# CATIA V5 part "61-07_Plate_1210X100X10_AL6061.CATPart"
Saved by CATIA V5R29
Part number: 61-07_Plate_580X100X10_AL6061
Bounding box of the stored display mesh (mm): x -290 to 290, y 0 to 10, z -50 to 50
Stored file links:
  C:\Users\Administrator\Desktop\10-14 작업\stopper\61-07_Plate_1210X100X10_AL6061.CATPart
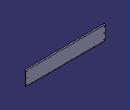
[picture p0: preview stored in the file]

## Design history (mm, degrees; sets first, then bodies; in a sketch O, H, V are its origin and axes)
Body1 (main body)
  Sketch1 on zx-plane, origin (0, 0, 0), H (-1, 0, 0), V (0, 0, 1)
    line L1 (290, 50) -> (290, -50)
    line L2 (290, -50) -> (-290, -50)
    line L3 (-290, -50) -> (-290, 50)
    line L4 (-290, 50) -> (290, 50)
    length L1 = 100
    length L4 = 580
    vertical: L1 V, L3 V
    horizontal: L2 H, L4 H
    equidistance: L1 L3 O, L2 L4 O
  Pad1: profile Sketch1, direction (0, 1, 0), length 10
  Sketch2 on start face of Pad1, origin (588.8761, 0, 35.2522), H (1, 0, 0), V (0, 0, 1)
    point P1 (-308.8761, 4.7478)
    reference projected line E1 (-298.8761, 14.7478) -> (-298.8761, -85.2522) from edge [start face of Pad1 | face of Pad1 from Sketch1.L3]
    reference projected line E2 (-878.8761, 14.7478) -> (-298.8761, 14.7478) from edge [start face of Pad1 | face of Pad1 from Sketch1.L4]
    distance P1 E1 = 10
    distance P1 E2 = 10
  Hole1: placed by Sketch2, at (280, 0, 40) direction (0, 1, 0), diameter 4.5, depth 10, V-bottom angle 120, counterbore diameter 8, counterbore depth 4.4
  DatumCurve1
  RectPattern1: of Hole1, direction 1 instances 3, spacing 40, along edge [start face of Pad1 | face of Pad1 from Sketch1.L3], direction 2 instances 2, spacing 560, along edge [start face of Pad1 | face of Pad1 from Sketch1.L4] reversed
  DatumCurve2 to DatumCurve4
  DatumSurface1
  DatumSurface2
